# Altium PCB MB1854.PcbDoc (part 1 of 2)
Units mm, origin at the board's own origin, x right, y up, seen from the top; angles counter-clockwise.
Board outline 50.11 x 30.1 mm, 4 copper layers (Top Layer, Signal Layer 1, Signal Layer 2, Bottom Layer), stack 1.556 mm thick; 50 components, 31 nets, 194 pads, 158 vias.
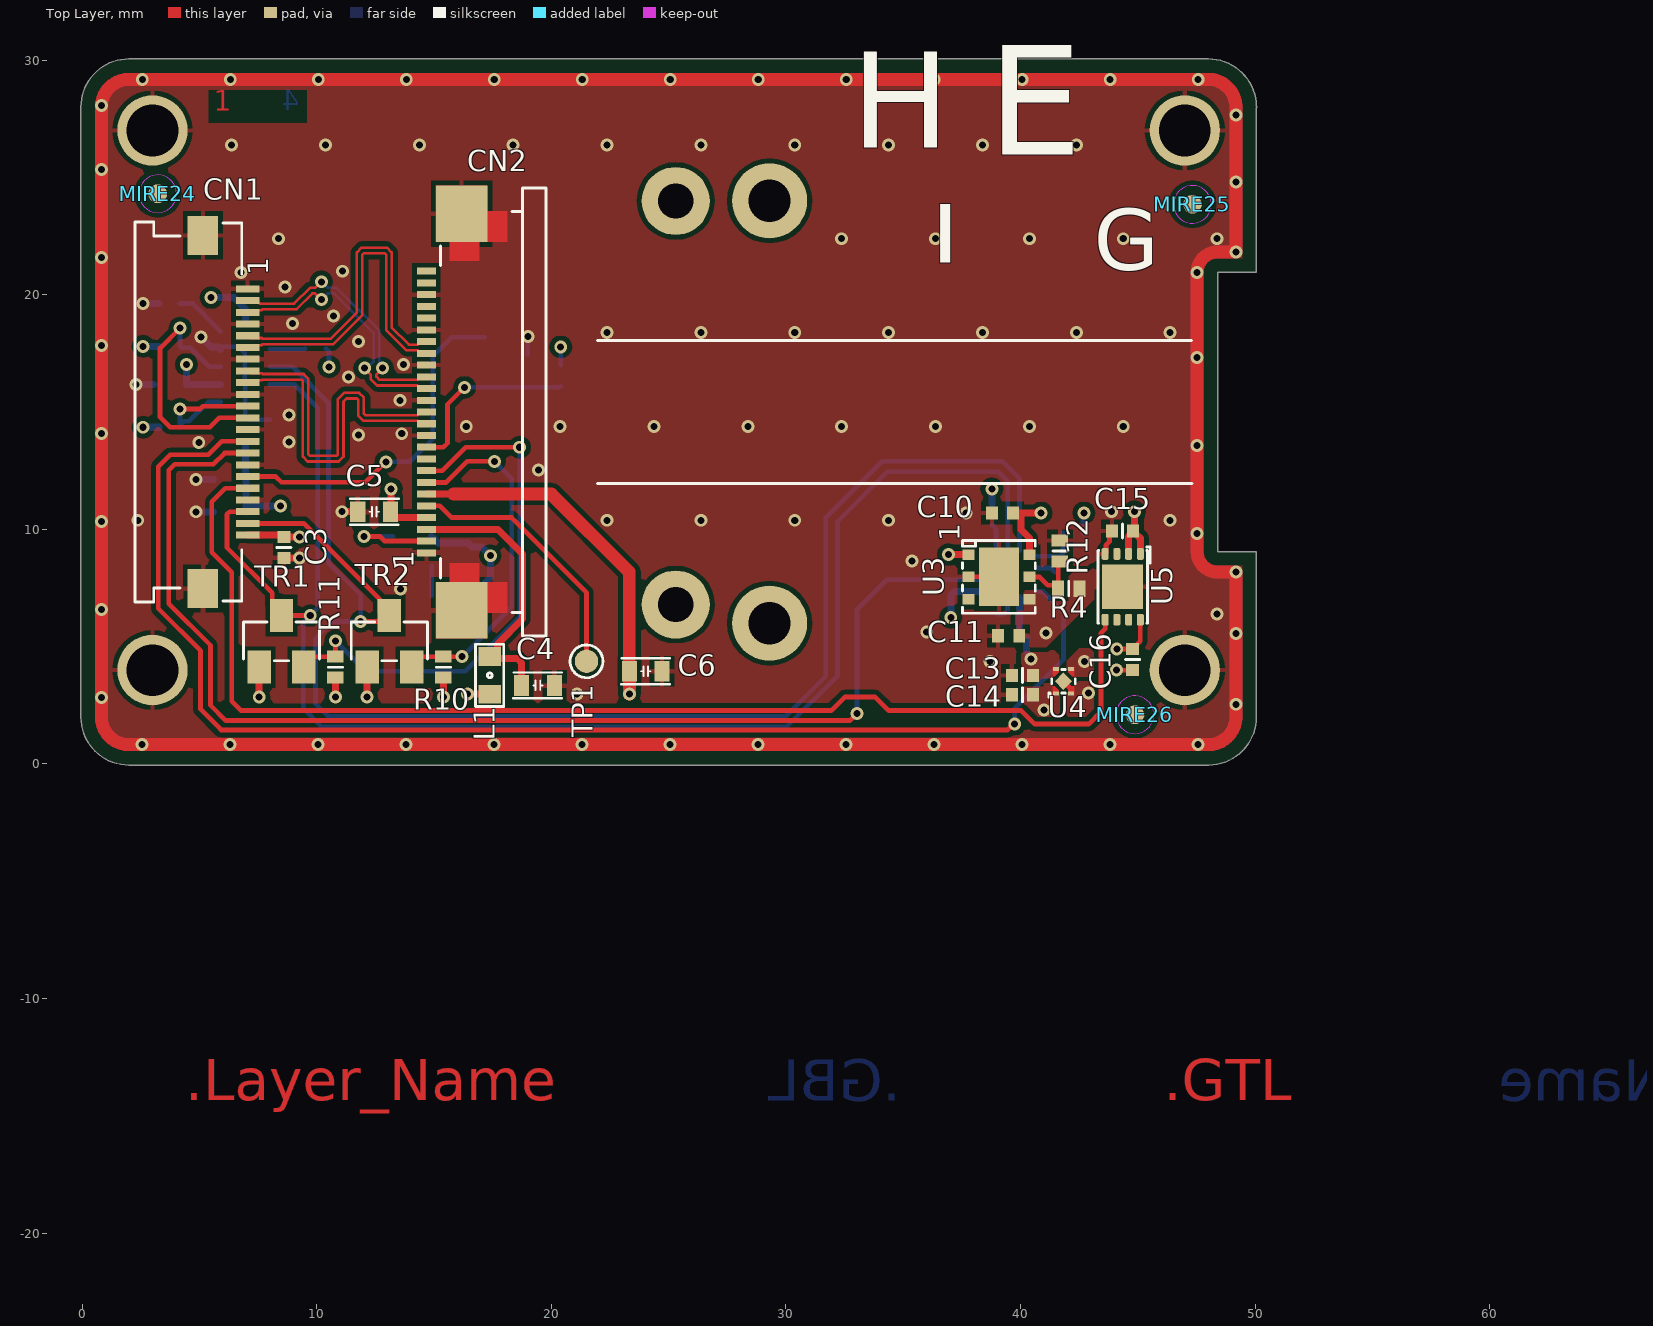
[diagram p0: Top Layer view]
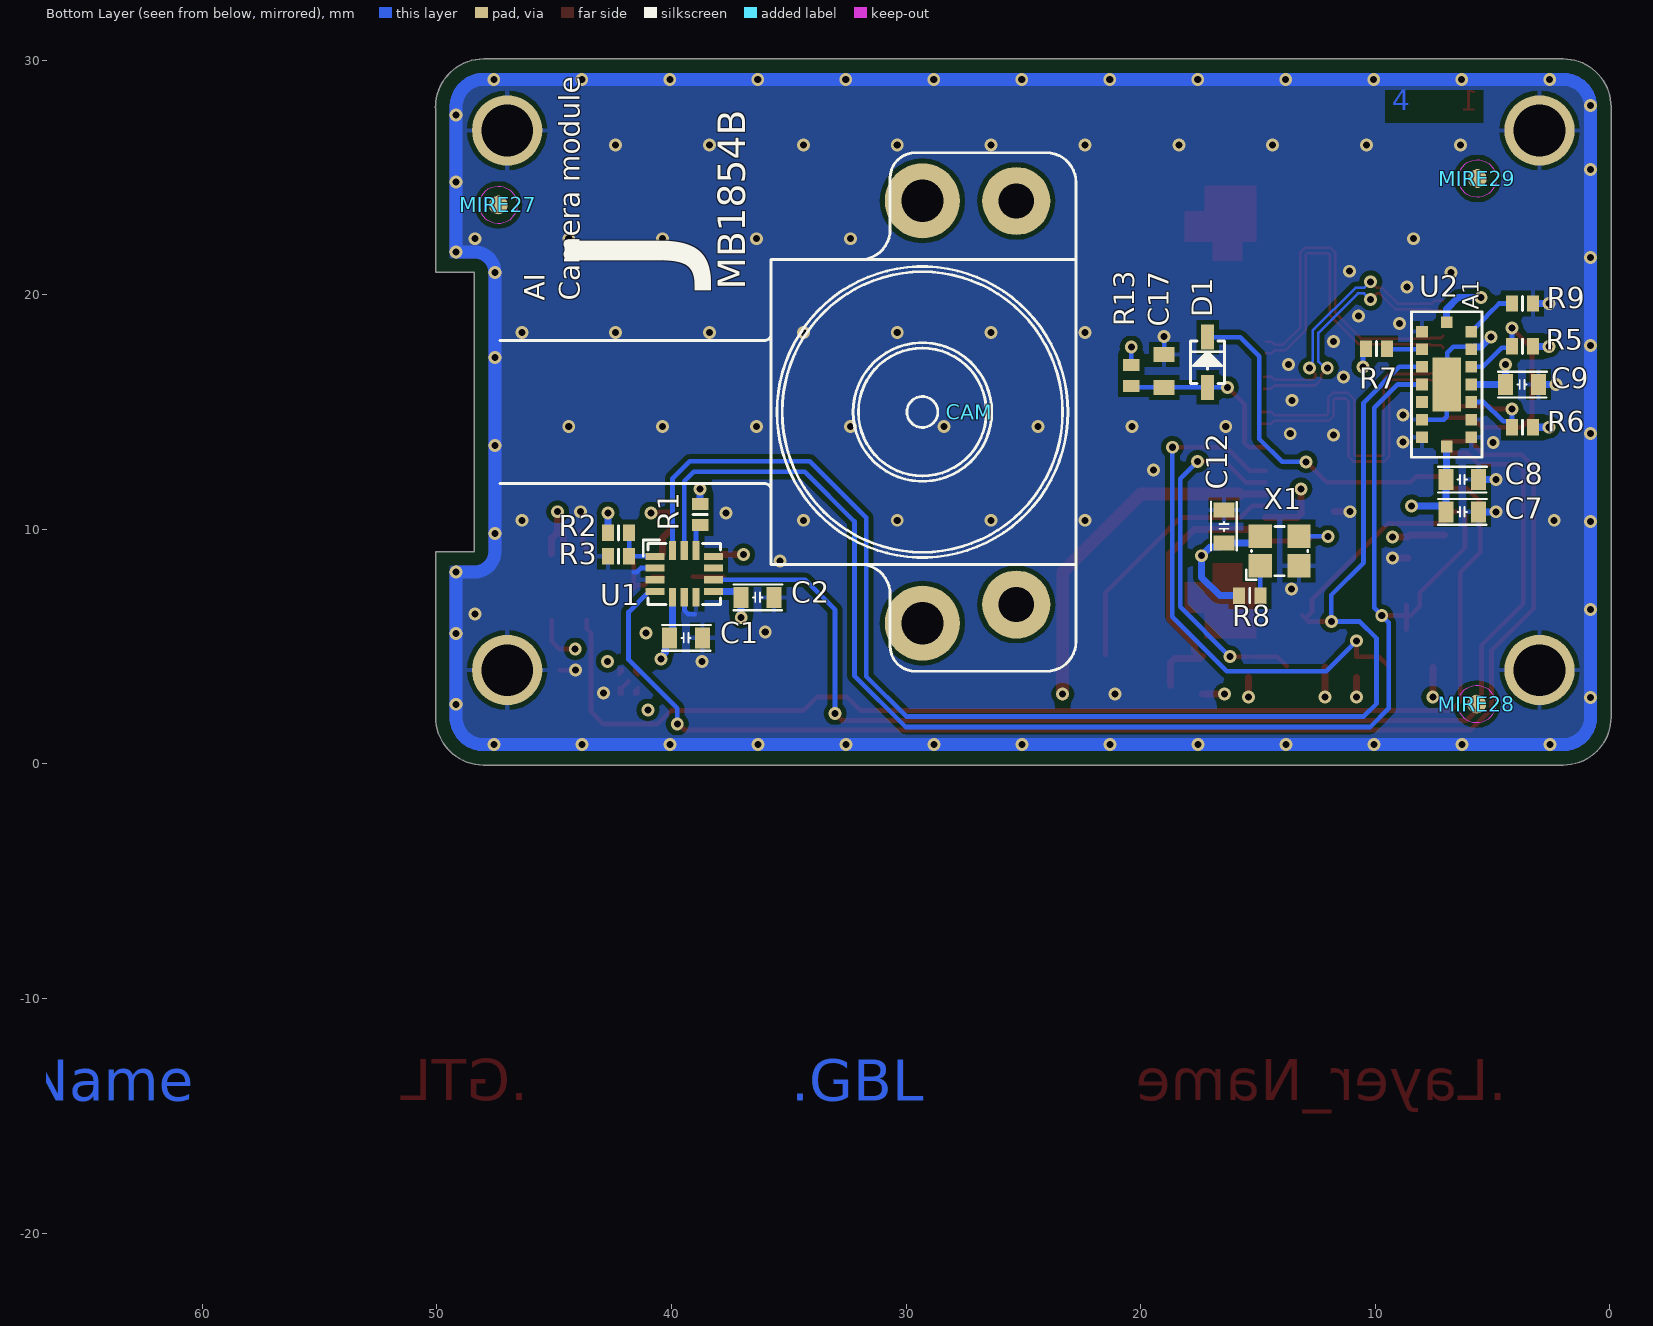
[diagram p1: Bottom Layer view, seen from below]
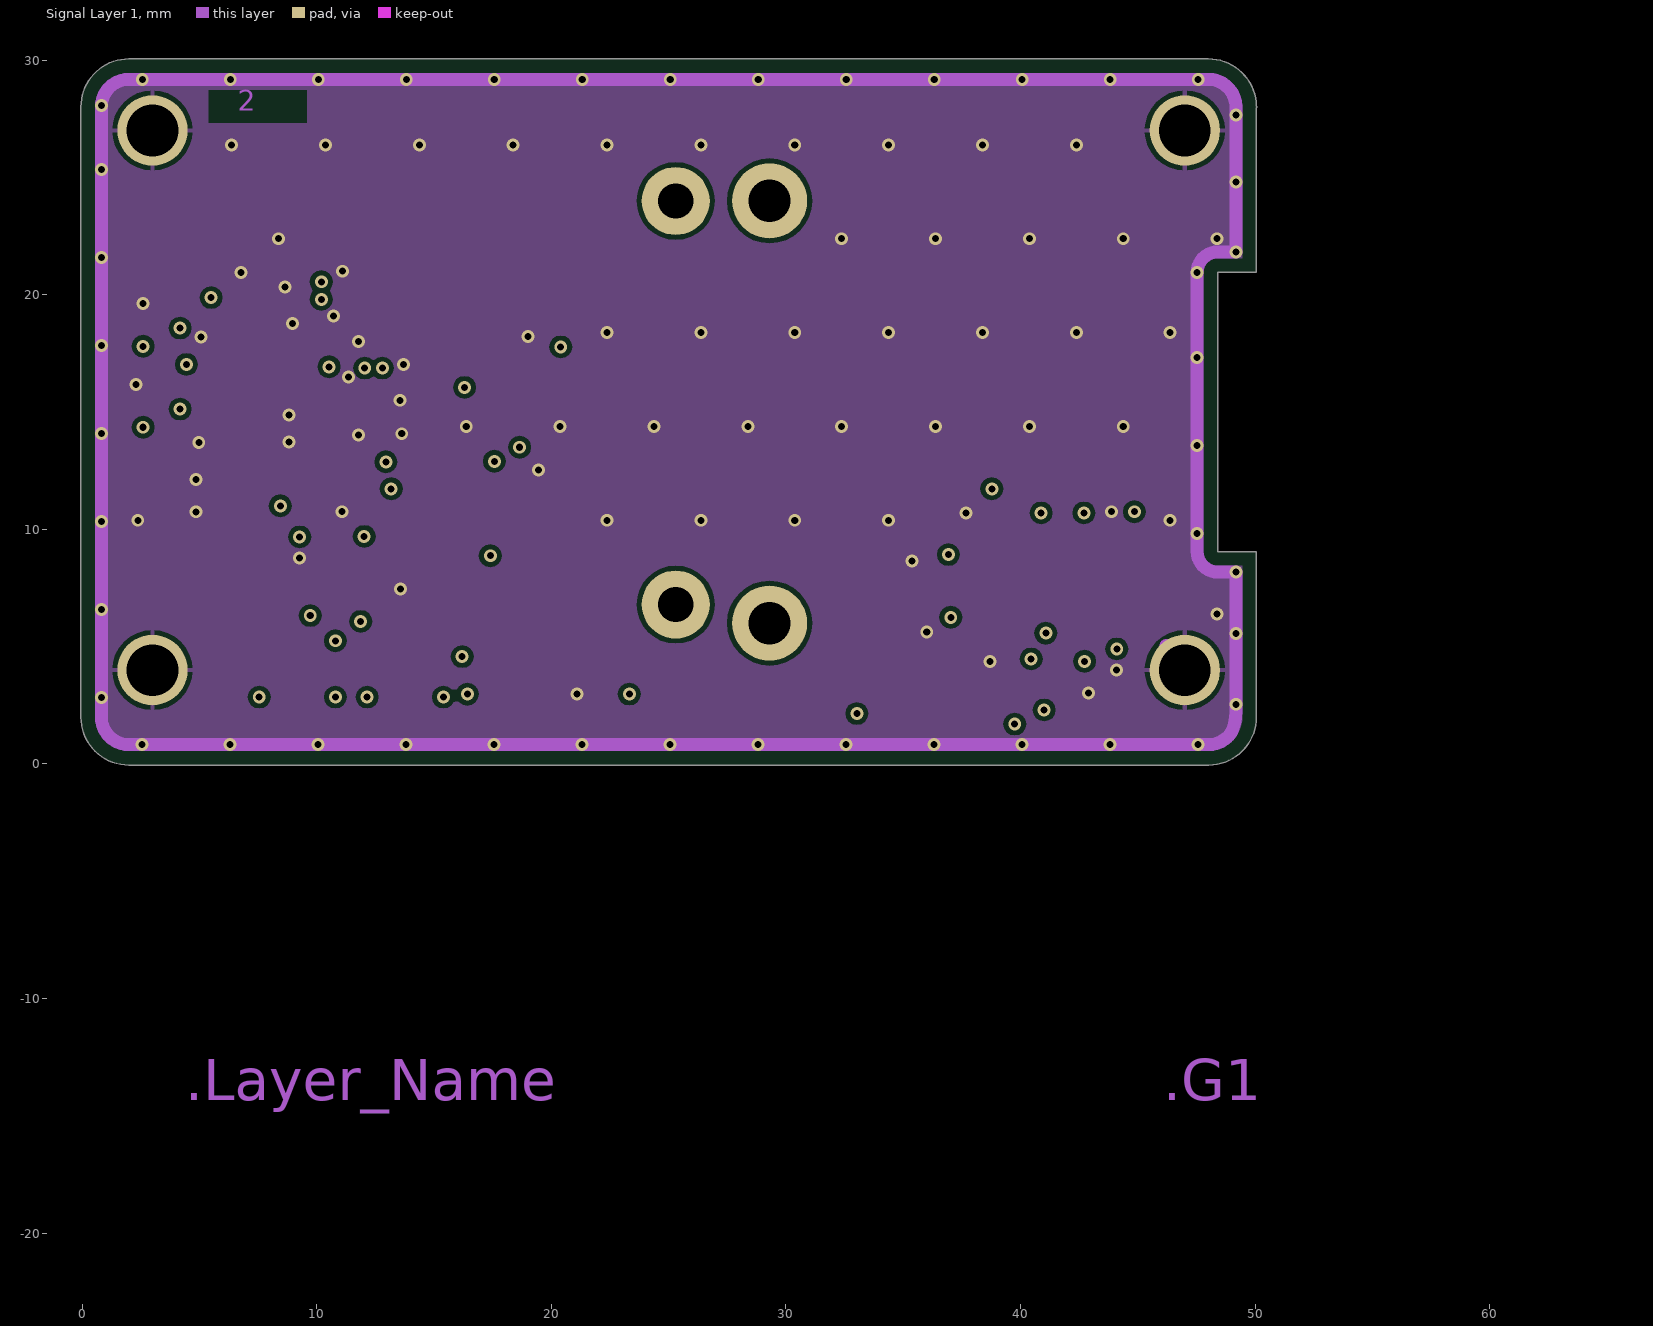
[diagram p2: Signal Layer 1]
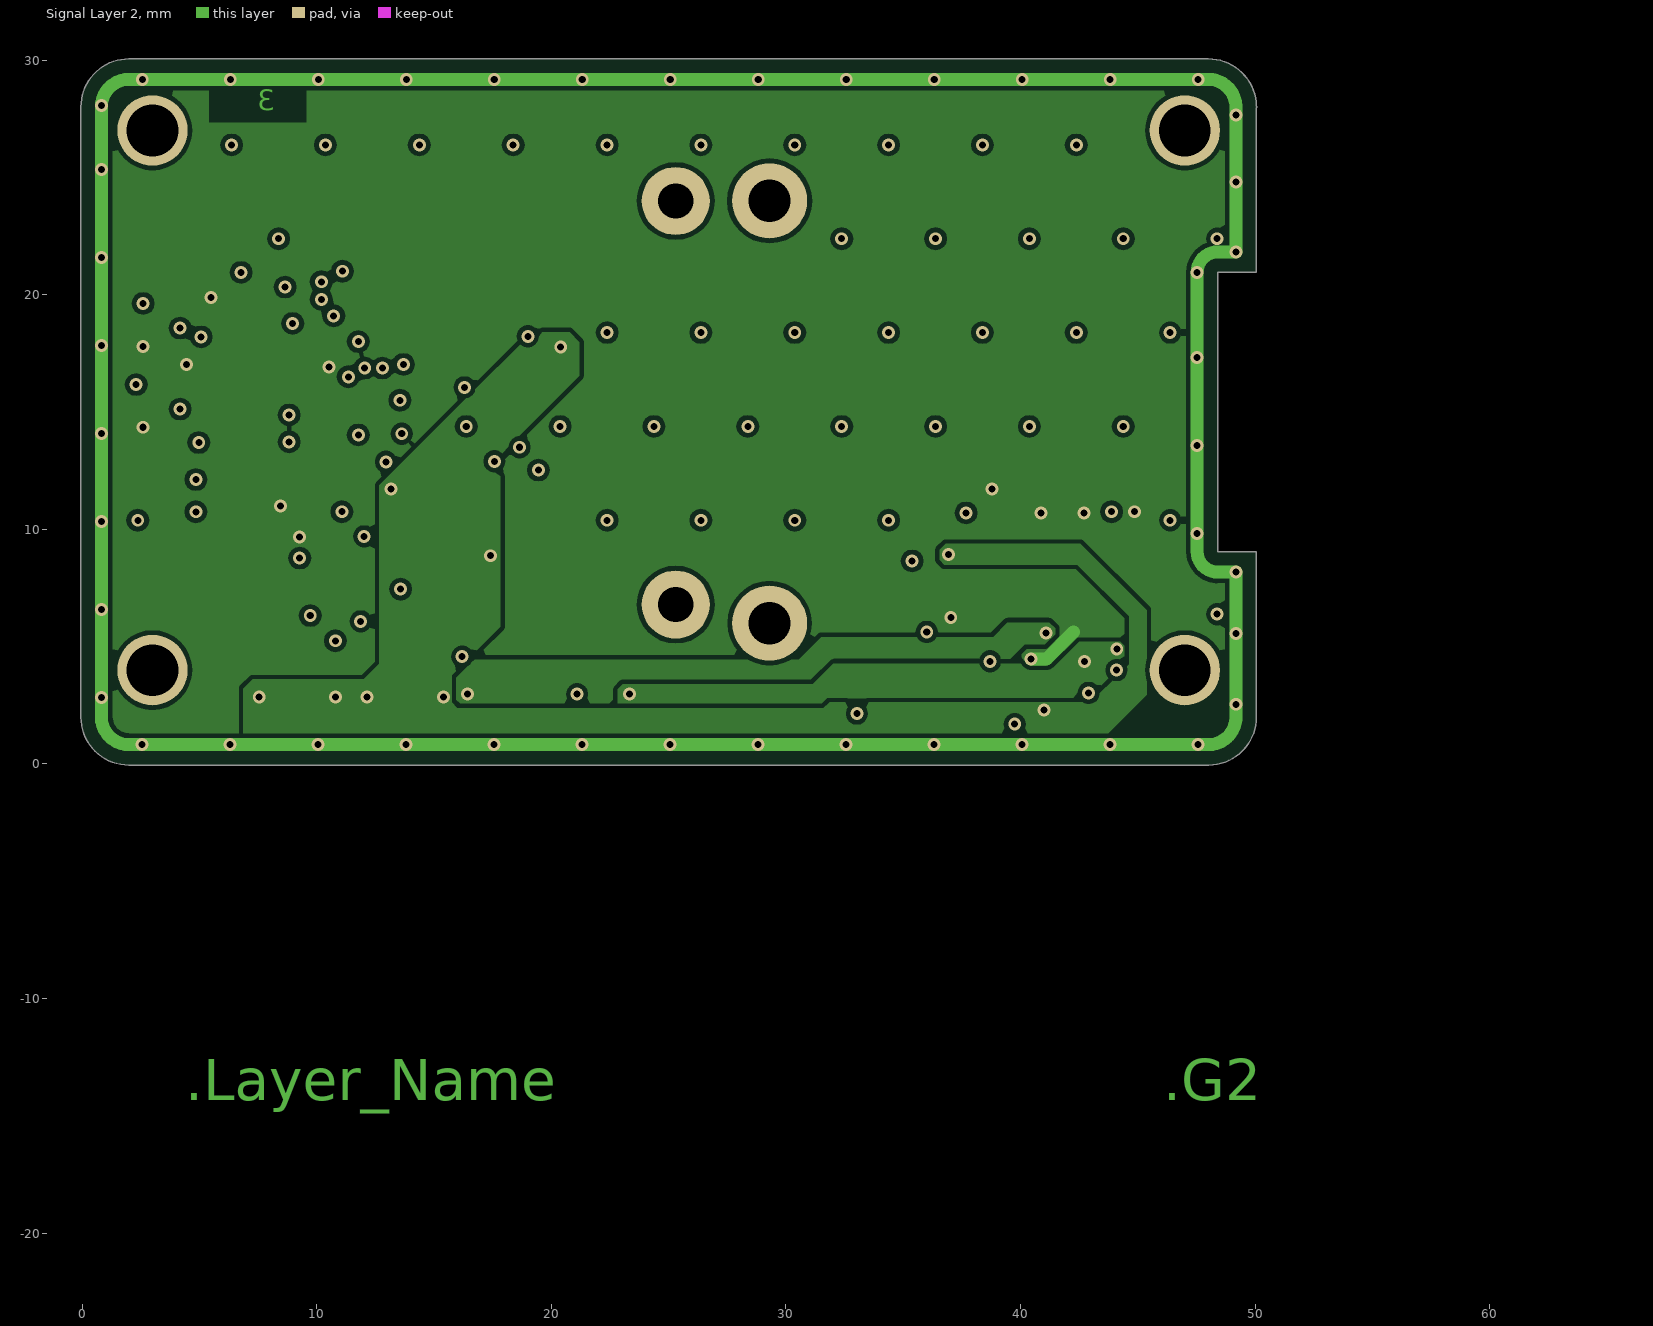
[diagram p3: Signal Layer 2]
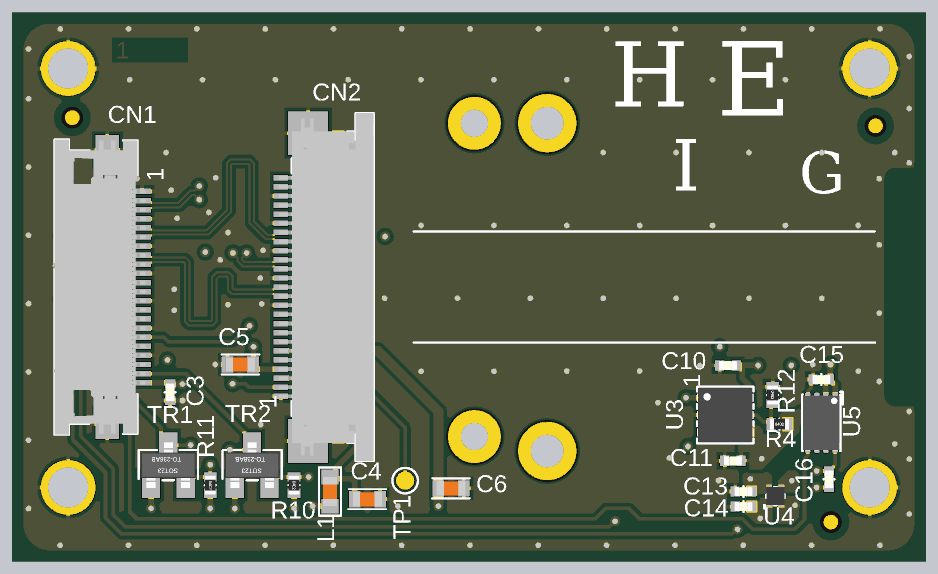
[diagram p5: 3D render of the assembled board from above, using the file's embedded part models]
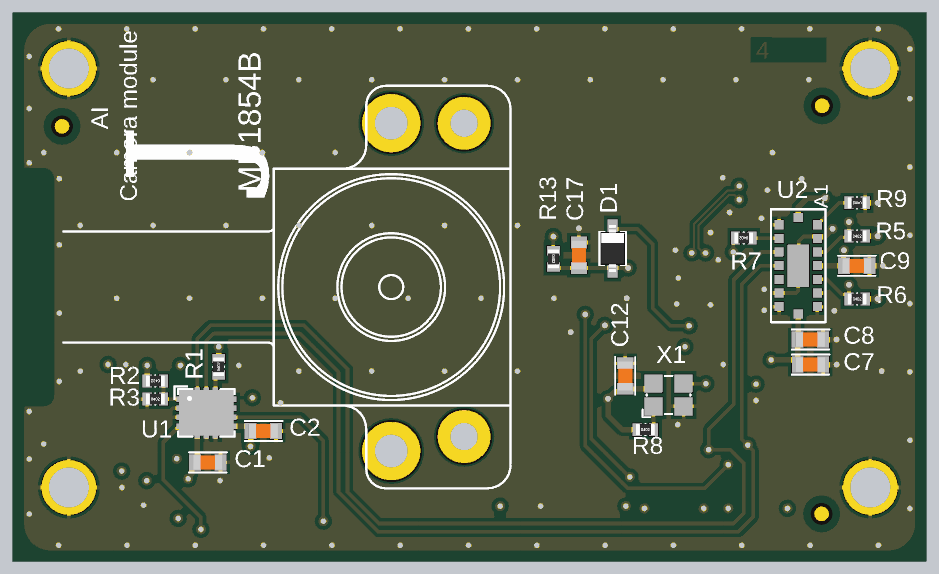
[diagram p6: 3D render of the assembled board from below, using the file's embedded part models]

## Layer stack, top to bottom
Top Solder: solder mask 0.015, Solder Resist, Dk 3.5
Top Layer: signal copper 0.037
Dielectric 2: prepreg 0.106, Dk 4.1
Signal Layer 1: signal copper 0.035
Dielectric 1: dielectric 1.2, Dk 4.2
Signal Layer 2: signal copper 0.035
Dielectric 3: prepreg 0.106, Dk 4.1
Bottom Layer: signal copper 0.037
Bottom Solder: solder mask 0.015, Solder Resist, Dk 3.5

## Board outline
-0.05,2 ccw(c2,2) 1.999,-0.05 ccw(c2,0) 2,-0.05 48.018,-0.05 ccw(c48.018,0) 48.022,-0.05 ccw(c48,2) 50.05,2 ccw(c50,2) 50.05,2.001 50.05,9 ccw(c50,9) 50,9.05 48.4,9.05 48.4,20.95 50,20.95 ccw(c50,21) 50.05,21 50.05,27.967 ccw(c50,28) 50.06,28 ccw(c50,28) 50.05,28.034 ccw(c48,28) 48,30.05 2.001,30.05 2,30.05 cw(c2,30) 2.001,30.05 2,30.05 ccw(c2,28) -0.05,28 ccw(c0,28) -0.05,28 -0.048,2.016 ccw(c0,2)

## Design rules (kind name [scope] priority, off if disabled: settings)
BoardOutlineClearance [All] p1: gap=0.3 ignorepadtopadclearanceinfootprint=FALSE except(0.6: Arc-OutlineEdge Track-OutlineEdge SMDPad-OutlineEdge THPad-OutlineEdge Via-OutlineEdge Fill-OutlineEdge Poly-OutlineEdge Region-OutlineEdge Text-OutlineEdge)
Clearance Clearance_Diff_GND [InNetClass('Paire_diff') vs InNet('GND')] p1: gap=0.3 ignorepadtopadclearanceinfootprint=TRUE except(0: Arc-Hole Track-Hole SMDPad-Hole THPad-Hole Via-Hole Fill-Hole Poly-Hole Region-Hole Text-Hole; 0.11: Arc-Arc Arc-Track Track-Track; 0.15: Arc-SMDPad Track-SMDPad; 0.2: SMDPad-SMDPad SMDPad-THPad SMDPad-Via SMDPad-Fill SMDPad-Poly SMDPad-Region SMDPad-Text)
Clearance [All] p2: gap=0.2 ignorepadtopadclearanceinfootprint=TRUE except(0: Arc-Hole Track-Hole SMDPad-Hole THPad-Hole Via-Hole Fill-Hole Poly-Hole Region-Hole Text-Hole; 0.11: Arc-Region Track-Via Track-Region SMDPad-Via SMDPad-Region THPad-Region Via-Region Fill-Region Poly-Region Region-Region; 0.13: Track-Track; 0.165: Arc-SMDPad Track-SMDPad)
ComponentClearance [All] p1: gap=0.2 collisioncheckmode=3 verticalgap=0.2 showdistances=FALSE
DiffPairsRouting DiffPairsRouting_CSI [InDifferentialPairClass('All Differential Pairs')] p1: maxlimit=0.254 minlimit=0.13 mostfreqgap=0.254 toplayer_maxgap=0.13 toplayer_prefgap=0.13 toplayer_minwidth=0.11 toplayer_maxwidth=0.11 toplayer_prefwidth=0.11 bottomlayer_maxgap=0.13 bottomlayer_prefgap=0.13 bottomlayer_minwidth=0.11 bottomlayer_maxwidth=0.11 bottomlayer_prefwidth=0.11 impedanceprofiledriven=TRUE impedanceprofileid={002CB140-4212-412A-BC71-8A519212D4D4} impedanceprofilevalue=100.000000 maxuncoupledlength=12.7
HoleSize [All] p1: absolutevalues=TRUE maxlimit=10 minlimit=0.025 maxpercent=80.000 minpercent=20.000
HoleToHoleClearance [All] p1: gap=0.45 allowstackedmicrovias=TRUE
Length LengthCSI [InNetClass('CSI')] p1: maxlimit=34.94 minlimit=33.67
MatchedLengths MatchedLengths_Inter_CSI [InNetClass('CSI')] p1: tolerance=1.27 checknetsindiffpair=FALSE checkdiffpairvsdiffpair=TRUE checkxsignals=TRUE checkothers=TRUE
MatchedLengths MatchedLengths_Intra_CSI [InDifferentialPairClass('CSI')] p2: tolerance=0.127 checknetsindiffpair=TRUE checkdiffpairvsdiffpair=FALSE checkxsignals=FALSE checkothers=FALSE
MinimumSolderMaskSliver [All] p1: minsoldermaskwidth=0.1
PlaneClearance [All] p1: clearance=0.6
PlaneConnect [All] p1: planeconnectstyle=Relief reliefexpansion=0.508 reliefentries=4 reliefconductorwidth=0.21 reliefairgap=0.21
PolygonConnect PolygonConnect_NO_FT [IsNamedPolygon('NO FT')] p1: connectstyle=Direct reliefconductorwidth=0.254 reliefentries=4 polygonreliefangle="90 Angle" airgapwidth=0.254
PolygonConnect [All] p2: thpad.connectstyle=Relief thpad.reliefconductorwidth=0.2 thpad.reliefentries=4 thpad.polygonreliefangle="90 Angle" thpad.airgapwidth=0.2 smdpad.connectstyle=Relief smdpad.reliefconductorwidth=0.2 smdpad.reliefentries=4 smdpad.polygonreliefangle="90 Angle" smdpad.airgapwidth=0.2 via.connectstyle=Direct via.reliefconductorwidth=0.2 via.reliefentries=4 via.polygonreliefangle="90 Angle" via.airgapwidth=0.2
RoutingVias [All] p1: holewidth=0.3 width=0.55 viastyle="Through Hole" minholewidth=0.3 minwidth=0.55 maxholewidth=0.3 maxwidth=0.55
SilkToSilkClearance [All] p1: silktosilkclearance=0.2
SilkToSolderMaskClearance [IsPad] p1: minsilkscreentomaskgap=0.2 clearancetoexposedcopper=TRUE
SolderMaskExpansion [All] p1: expansion=0.102 istentingtop=FALSE
ViasUnderSMD [All] p1: allowed=FALSE
Width [All] p1: maxlimit=1 minlimit=0.1 preferedwidth=0.2
21 further rules are at their usual default settings.

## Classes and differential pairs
component class U_MB1854: C1 C2 C3 C4 C5 C6 C7 C8 C9 C10 C11 C12 C13 C14 C15 C16 C17 CN1 CN2 D1 L1 R1 R2 R3 R4 R5 R6 R7 R8 R9 R10 R11 R12 R13 TP1 TR1 TR2 U1 U2 U3 U4 U5 X1
differential pair CSI_D1: +CSI_D1_P -CSI_D1_N
differential pair CSI_D0: +CSI_D0_P -CSI_D0_N
differential pair CSI_CLK: +CSI_CLK_P -CSI_CLK_N

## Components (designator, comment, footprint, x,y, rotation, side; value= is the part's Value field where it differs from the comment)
C1 "Capacitor" C0603 39.375,5.375 r0 bottom value=100nF
C2 "Capacitor" C0603 36.325,7.1 r0 bottom value=100nF
C3 "Capacitor" C0402 8.6,9.225 r90 top value=1uF
C4 "Capacitor" C0603 19.428,3.35 r0 top value=100nF
C5 "Capacitor" C0603 12.45,10.75 r180 top value=100nF
C6 "Capacitor" C0603 24.023,3.95 r0 top value=100nF
C7 "Capacitor" C0603 6.292,10.745 r0 bottom value=4.7uF
C8 "Capacitor" C0603 6.295,12.12 r0 bottom value=100nF
C9 "Capacitor" C0603 3.745,16.168 r0 bottom value=100nF
C10 "Capacitor" C0402 39.228,10.7 r0 top value=10uF
C11 "Capacitor" C0402 39.493,5.461 r0 top value=10uF
C12 "Capacitor" C0603 16.453,10.125 r270 bottom value=100nF
C13 "Capacitor" C0402 40.075,3.775 r0 top value=1uF
C14 "Capacitor" C0402 40.078,2.95 r0 top value=1uF
C15 "Capacitor" C0402 44.35,9.925 r0 top value=1uF
C16 "Capacitor" C0402 44.775,4.45 r90 top value=10uF
C17 "Capacitor" C0603 19,16.75 r90 bottom value=100nF
CAM "Comment" CAM_DRAWING_AS-BC538A3M6-63 29.303,15 r270 bottom locked
CN1 "54548-2271" CON_MOLEX_54548-2271 6.803,15 r270 top value=FPC_54548-2271
CN2 "52437-2533" CON_MOLEX_52437-2533 15.425,15 r90 top
D1 "BAT60JFILM" DIO_SOD323 17.15,17.12 r90 bottom
L1 "BEAD" L0603 17.375,3.775 r90 top value="600R @ 100MHz"
MIRE24 "Comment" MIRE_PLACE_SMD_0P8MM 3.225,24.3 r180 top
MIRE25 "Comment" MIRE_PLACE_SMD_0P8MM 47.325,23.85 r180 top
MIRE26 "Comment" MIRE_PLACE_SMD_0P8MM 44.875,2.1 r180 top
MIRE27 "Comment" MIRE_PLACE_SMD_0P8MM 47.375,23.825 r180 bottom
MIRE28 "Comment" MIRE_PLACE_SMD_0P8MM 5.675,2.55 r180 bottom
MIRE29 "Comment" MIRE_PLACE_SMD_0P8MM 5.65,24.95 r180 bottom
R1 "Resistor" R0402 38.775,10.625 r90 bottom value=10K
R2 "" R0402 42.253,9.85 r0 bottom value=4K7
R3 "" R0402 42.253,8.85 r180 bottom value=4K7
R4 "Resistor" R0402 42.053,7.475 r0 top value=19K6
R5 "Resistor" R0402 3.725,17.8 r180 bottom value=47K
R6 "Resistor" R0402 3.725,14.35 r180 bottom value=47K
R7 "Resistor" R0402 9.95,17.7 r0 bottom value=47K
R8 "Resistor" R0402 15.35,7.175 r180 bottom value=10K
R9 "Resistor" R0402 3.725,19.625 r0 bottom value=47K
R10 "Resistor" R0402 15.4,4.125 r270 top value=4K7
R11 "Resistor" R0402 10.8,4.125 r270 top value=4K7
R12 "Resistor" R0402 41.678,9.075 r270 top value=15K
R13 "Resistor" R0402 20.4,16.55 r270 bottom value=10K
TP1 "Test Point" TP_SMD_1MM 21.5,4.375 r0 top
TR1 "BSN20" MOS_SOT23 8.5,5.225 r0 top value=FDV301N
TR2 "BSN20" MOS_SOT23 13.1,5.225 r0 top value=FDV301N
U1 "ISM330DLCTR" ICC_LGA14_3X2P5_P050 39.453,8.1 r180 bottom
U2 "VL53L5CXV0GC/1" ICC_LGA16_6P4X3_P075_H1P5 6.958,16.175 r90 bottom
U3 "ST1L05BPUR" ICC_DFN6-EPAD_3X3_P095 39.078,7.975 r270 top
U4 "LD39020" REG_XDFN4-EPAD_CASE-711AJ_1X1_H0P4_P065 41.828,3.525 r0 top value=LD39020ADTPU18R
U5 "ST1L08SPU12R" ICC_DFN8-EPAD_2X3_P050_H0P9 44.353,7.55 r0 top
X1 "OSCILLATOR_4_PINS" OSC_NDK_NZ2520SB_4P 14.078,9.075 r180 bottom value=24MHz

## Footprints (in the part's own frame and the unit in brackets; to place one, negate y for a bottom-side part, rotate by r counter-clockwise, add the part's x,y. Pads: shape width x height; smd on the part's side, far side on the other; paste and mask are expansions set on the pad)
C0402 [mm]
  rect 0.51x0.56 smd mask+0.05: 1(-0.45,0) 2(0.45,0)
  silkscreen extent 0,-0.3 0,0.3, body extent -0.5,-0.3 0.5,0.3, height 0.4
C0603 [mm]
  rect 0.64x0.89 smd mask+0.05: 1(-0.7,0) 2(0.7,0)
  silkscreen extent -1.05,-0.55 1.02,0.55, body extent -0.9,-0.5 0.9,0.5, height 1.4
CAM_DRAWING_AS-BC538A3M6-63 [mm] "MCD-02783"
  round 3.2 hole 1.8 mask+0.102: 1(-9,0) 1(9,0)
  round 2.9 hole 1.5 mask+0.102: 1(-8.993,4) 1(8.207,4)
  silkscreen extent -11.05,-18 11.05,6.55, body extent -23.01,-6.9 11.05,12.51, height 24.2
CON_MOLEX_52437-2533 [mm] "MCD-XXXXX"
  rect 0.3x0.8 smd mask+0.05: 1(-6,0.75) 2(-5.5,0.75) 3(-5,0.75) 4(-4.5,0.75) 5(-4,0.75) 6(-3.5,0.75) 7(-3,0.75) 8(-2.5,0.75) 9(-2,0.75) 10(-1.5,0.75) 11(-1,0.75) 12(-0.5,0.75) 13(0,0.75) 14(0.5,0.75) 15(1,0.75) 16(1.5,0.75) 17(2,0.75) 18(2.5,0.75) 19(3,0.75) 20(3.5,0.75) 21(4,0.75) 22(4.5,0.75) 23(5,0.75) 24(5.5,0.75) 25(6,0.75)
  rect 2.4x2.2 smd mask+0.05: S1(-8.45,-0.75) S2(8.45,-0.75)
  Top Layer region: 9.65,0.35 7.25,0.35 7.25,-0.25 6.45,-0.25 6.45,-1.5 7.25,-1.5 7.25,-2.7 8.55,-2.7 8.55,-1.85 9.65,-1.85
  Top Layer region: -9.65,0.35 -7.25,0.35 -7.25,-0.25 -6.45,-0.25 -6.45,-1.5 -7.25,-1.5 -7.25,-2.7 -8.55,-2.7 -8.55,-1.85 -9.65,-1.85
  silkscreen extent -9.55,-4.35 9.55,0.15, body extent -9.55,-4.35 9.55,0.85, height 2
CON_MOLEX_54548-2271 [mm] "MCD-02565"
  rect 0.3x1 smd paste+0 mask+0.05: 1(-5.25,0.25) 2(-4.75,0.25) 3(-4.25,0.25) 4(-3.75,0.25) 5(-3.25,0.25) 6(-2.75,0.25) 7(-2.25,0.25) 8(-1.75,0.25) 9(-1.25,0.25) 10(-0.75,0.25) 11(-0.25,0.25) 12(0.25,0.25) 13(0.75,0.25) 14(1.25,0.25) 15(1.75,0.25) 16(2.25,0.25) 17(2.75,0.25) 18(3.25,0.25) 19(3.75,0.25) 20(4.25,0.25) 21(4.75,0.25) 22(5.25,0.25)
  rect 1.65x1.3 smd paste+0 mask+0.05: S1(-7.525,-1.65) S2(7.525,-1.65)
  silkscreen extent -8.1,-4.55 8.1,0, body extent -8.1,-4.55 8.1,0.45, height 1.18
DIO_SOD323 [mm]
  rect 1.06x0.54 smd mask+0.05: 1(-1.07,0) 2(1.07,0)
  silkscreen extent -0.9,-0.72 0.9,0.72, body extent -1.3,-0.78 1.3,0.78, height 1.17
ICC_DFN6-EPAD_3X3_P095 [mm]
  rect 0.45x0.5 smd mask+0.05: 1(-0.95,-1.3) 2(0,-1.3) 3(0.95,-1.3) 4(0.95,1.3) 5(0,1.3) 6(-0.95,1.3)
  rect 2.5x1.7 smd mask+0.05: EP(0,0)
  silkscreen extent -1.55,-1.55 1.55,1.55, body extent -1.55,-1.55 1.55,1.55, height 1
ICC_DFN8-EPAD_2X3_P050_H0P9 [mm] "MCD-02312"
  rrect50% 0.3x0.5 smd mask+0.05: 1(0.75,1.4) 2(0.25,1.4) 3(-0.25,1.4) 4(-0.75,1.4) 5(-0.75,-1.4) 6(-0.25,-1.4) 7(0.25,-1.4) 8(0.75,-1.4)
  rect 1.75x1.9 smd mask+0.05: 9(0,0)
  silkscreen extent -1.05,-1.55 1.17,1.7, body extent -1,-1.52 1,1.52, height 0.9
ICC_LGA14_3X2P5_P050 [mm] "MCD-01387"
  rect 0.8x0.3 smd mask+0.05: 1(-1.25,0.75) 2(-1.25,0.25) 3(-1.25,-0.25) 4(-1.25,-0.75) 8(1.25,-0.75) 9(1.25,-0.25) 10(1.25,0.25) 11(1.25,0.75)
  rect 0.3x0.8 smd mask+0.05: 5(-0.5,-1) 6(0,-1) 7(0.5,-1) 12(0.5,1) 13(0,1) 14(-0.5,1)
  silkscreen extent -1.75,-1.3 1.55,1.45, body extent -1.55,-1.3 1.55,1.3, height 0.86
ICC_LGA16_6P4X3_P075_H1P5 [mm] "MCD-02257"
  rect 0.5x0.5 smd mask+0.05: A1(2.25,-1.05) A2(1.5,-1.05) A3(0.75,-1.05) A4(0,-1.05) A5(-0.75,-1.05) A6(-1.5,-1.05) A7(-2.25,-1.05) B1(2.65,0) B7(-2.65,0) C1(2.25,1.05) C2(1.5,1.05) C3(0.75,1.05) C4(0,1.05) C5(-0.75,1.05) C6(-1.5,1.05) C7(-2.25,1.05)
  rect 2.316x1.2 smd mask+0.05: B4(0,0)
  silkscreen extent -3.1,-1.5 3.1,1.5, body extent -3.1,-1.5 3.1,1.5, height 1.51
L0603 [mm]
  rect 0.8x0.95 smd mask+0.05: 1(-0.8,0) 2(0.8,0)
  silkscreen extent -1.33,-0.6 1.33,0.6, body extent -0.87,-0.47 0.87,0.47, height 0.95
MIRE_PLACE_SMD_0P8MM [mm]
  round 0.8 smd paste-10 mask+0.2: 1(0,0)
  Top Layer keep-out circle w0.01: c0,0 r0.804
MOS_SOT23 [mm]
  rect 1x1.4 smd mask+0.05: 1(-0.95,-1.1) 2(0.95,-1.1) 3(0,1.1)
  silkscreen extent -1.63,-0.82 1.63,0.82, body extent -1.56,-1.25 1.56,1.25, height 1.1
OSC_NDK_NZ2520SB_4P [mm]
  rect 1x1 smd mask+0.05: 1(-0.825,-0.625) 2(0.825,-0.625) 3(0.825,0.625) 4(-0.825,0.625)
  silkscreen extent -1.43,-1.22 1.2,1.05, body extent -1.3,-1.05 1.3,1.05, height 0.91
R0402 [mm]
  rect 0.51x0.7 smd mask+0.05: 1(-0.45,0) 2(0.45,0)
  silkscreen extent 0,-0.3 0,0.3, body extent -0.52,-0.3 0.52,0.3, height 0.4
REG_XDFN4-EPAD_CASE-711AJ_1X1_H0P4_P065 [mm] "MCD-01613"
  rect 0.26x0.17 smd paste-10 mask-10: 1(-0.325,-0.515) 2(0.325,-0.515) 3(0.325,0.515) 4(-0.325,0.515)
  rect 0.52x0.52 smd rot 45 paste+0 mask+0.038: 5(0,0)
  Top Layer region: 0.455,-0.6 0.195,-0.6 0.195,-0.39 0.375,-0.21 0.455,-0.21
  Top Layer region: -0.455,-0.6 -0.195,-0.6 -0.195,-0.39 -0.375,-0.21 -0.455,-0.21
  Top Layer region: 0.455,0.6 0.195,0.6 0.195,0.39 0.375,0.21 0.455,0.21
  Top Layer region: -0.455,0.6 -0.195,0.6 -0.195,0.39 -0.375,0.21 -0.455,0.21
  Top Layer lines w0.001: 0.035,-0.33 0.035,-0.33
  silkscreen extent -0.63,-0.67 0.5,0.5, body extent -0.5,-0.5 0.5,0.5, height 0.44
TP_SMD_1MM [mm]
  round 1 smd paste-10 mask+0.05: 1(0,0)
  silkscreen extent -0.7,-0.7 0.7,0.7

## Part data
C1 C2 C4 C5 C6 C8 C9 C12 C17: library part MCD-00211, "Capacitor, MLCC, 100nF, 16V, X7R, 10%, 0603, T=0,8mm", Manufacturer=YAGEO, Manufacturer_Part_Number=CC0603KRX7R7BB104, Package=0603
C3 C13 C14 C15: library part MCD-00095, "Capacitor, MLCC, 1uF, 25V, X5R, +/-10%, 0402, T=0,5mm", Alternate_Manufacturer=MURATA, Alternate_Manufacturer_Part_Number=GRM155R60J105KE19, Manufacturer_Part_Number=GRM155R61E105KA12, Package=0402
C7: library part MCD-00009, "Capacitor, MLCC, 4.7uF, 16V, X5R, +/-10%, 0603, T=0.8mm", Alternate_Manufacturer=N/A, Manufacturer=YAGEO, Manufacturer_Part_Number=CC0603KRX5R7BB475, Package=0603
C10 C11 C16: library part MCD-01532, "Capacitor, MLCC, 10uF, 10V, X5R, +/-20%, 0402, T=0.5mm", Manufacturer=MURATA, Manufacturer_Part_Number=GRM155R61A106ME11, Package=0402
CN1: library part MCD-02565, "Socket_FFC/FPC, 22pins, 0.5mm, SMD, T=1.2mm", Manufacturer=MOLEX
CN2: library part MCD-02922, "Socket_FFC/FPC, 25pins, 0.5mm, RA, SMD, T=2mm", Manufacturer=MOLEX
D1: library part MCD-00034, Manufacturer=STMICROELECTRONICS, Manufacturer_HQ_COO=EU
L1: library part MCD-00047, "SMD Chip ferrite bead, 600R@100MHz +/-25%, 350mA, 500mohm DC, 0603, T=0.8mm", Manufacturer=TAI-TECH, Manufacturer_Part_Number=FCM1608KF-601T03, Package=0603
R1: library part MCD-00053, "Resistor, 10K, 0402, +/-1%, 1/16W", Alternate_Manufacturer=N/A, Manufacturer=YAGEO, Manufacturer_Part_Number=RC0402FR-0710KL, Package=0402
R2 R3 R10 R11: library part MCD-00065, "Resistor,4K7,0402,1%,1/16W", Alternate_Manufacturer=YAGEO, Alternate_Manufacturer_Part_Number=RT0402FRE074K7L, Manufacturer_Part_Number=RC0402FR-074K7L, Package=0402
R4: library part MCD-00344, "Resistor, 19K6, 0402, +/-1%, 1/16W", Manufacturer=YAGEO, Manufacturer_Part_Number=RC0402FR-0719K6L, Package=0402
R5 R6 R7 R9: library part MCD-00063, "Resistor, 47K, 0402, +/-1%, 1/16W", Alternate_Manufacturer=N/A, Manufacturer=YAGEO, Manufacturer_Part_Number=RC0402FR-0747KL, Package=0402
R8 R13: library part MCD-00053, "Resistor, 10K, 0402, +/-1%, 1/16W", Manufacturer=YAGEO, Manufacturer_Part_Number=RC0402FR-0710KL, Package=0402
R12: library part MCD-01943, "Resistor, 15K, 0402, +/-1%, 1/16W", Manufacturer=YAGEO, Manufacturer_Part_Number=RC0402FR-0715KL, Package=0402
TP1: library part MCD-00074, "Test Point 1mm", Manufacturer=N/A
TR1 TR2: library part MCD-02156, "MOSFET, N-Channel , Vds: 25V, Id: 0,22A, Vgs(th): 1.06V, Vgs(max): +/-8V, Rdson:5ohm@Vgs=2.7V, Qg=0,49nC", Alternate_Manufacturer=N/A, Manufacturer="ON SEMICONDUCTOR", Manufacturer_Part_Number=FDV301N, Package=SOT23-3
U1: library part MCD-01714, "iNEMO inertial module: 3D accelerometer and 3D gyroscope, with digital output for industrial applications", Manufacturer=STMICROELECTRONICS, Manufacturer_HQ_COO=EU, Package=LGA-14L
U2: library part MCD-02590, "Time-of-Flight 8x8 multizone ranging sensor with wide field of view", Manufacturer=STMICROELECTRONICS, Package="Optical LGA16"
U3: library part MCD-00581, "LDO Linear Voltage Regulator IC Positive Adjustable 1 Output Adjustable 1.3A 6-DFN (3x3)", Manufacturer=STMICROELECTRONICS, Manufacturer_HQ_COO=EU, Package="DFN6 (3x3)"
U4: library part MCD-02224, "LDO, output 1V8, 200 mA very low quiescent current", Alternate_Manufacturer=N/A, Manufacturer=STMICROELECTRONICS, Manufacturer_HQ_COO=EU, Manufacturer_Part_Number=LD39020ADTPU18R, Package=DFN4
U5: library part MCD-02920, "LDO, fixe 1V2, Input 1V to 5.5V, 0.8A", Manufacturer=STMICROELECTRONICS, Package=DFN-8
X1: library part MCD-01976, "Oscillator, SPXO, 24Mhz, +/-50ppm, 3V3, square wave, 2.5x2mm", Manufacturer=NDK, Manufacturer_Part_Number=NZ2520SH-24MHZ-END4869D, Package=2.5x2mm

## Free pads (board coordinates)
  round 3 hole 2.2 paste+0.025 mask+0.05: 1(3,4) 1(3,27) 1(47,4) 1(47,27)
  round 0.508 on Mech16: 1(16.06,-21.253) 1(64.915,-21.261)

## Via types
v1: diameter 0.55, hole 0.3, Top Layer to Bottom Layer, tented both sides, 158 vias

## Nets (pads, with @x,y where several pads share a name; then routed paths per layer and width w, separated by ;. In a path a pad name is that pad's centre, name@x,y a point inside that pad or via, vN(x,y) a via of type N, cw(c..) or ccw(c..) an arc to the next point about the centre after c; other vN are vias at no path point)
1V2: C6.1 C16.2 CN2.6 U4.3 U5.8 | length 17.3
  Top Layer w0.2: v1(44.1,4.9) C16.2@44.775,4.9 44.8,4.9 44.955,5.055 44.955,5.08 45.103,5.228 U5.8@45.103,6.15
  Top Layer w0.3: CN2.6@14.675,11.5 15.825,11.5
  Top Layer w0.55: 15.825,11.5 20,11.5 23.323,8.177 23.323,3.781 23.324,3.78 v1(23.324,2.976)
  other v1: 42.725,4.375
1V8: C5.1 C12.2 C14.2 CN2.4 R8.1 R10.2 R11.2 R13.1 TR1.1 TR2.1 U3.1 U4.1 X1.4 | length 14.2
  Top Layer w0.3: v1(7.55,2.85) TR1.1@7.55,4.125 ; v1(10.8,2.85) R11.2@10.8,3.675 ; v1(12.15,2.85) TR2.1@12.15,4.125 ; v1(13.175,11.725) 13.175,10.775 C5.1@13.15,10.75 13.15,10.67 13.32,10.5 CN2.4@14.675,10.5 ; v1(15.4,2.85) R10.2@15.4,3.675 ; v1(36.925,8.925) U3.1@37.778,8.925
  Bottom Layer w0.2: R13.1@20.4,17 v1(20.4,17.775)
  Bottom Layer w0.3: X1.4@14.903,9.7 15.178,9.425 C12.2@16.453,9.425 16.623,9.255 17.02,9.255 v1(17.4,8.875) 17.4,7.95 16.625,7.175 R8.1@15.8,7.175
  other v1: 41,2.3
2V8: C11.2 L1.1 R4.2 U3.4 | length 1
  Top Layer w0.3: v1(16.422,2.975) L1.1@17.375,2.975
  other v1: 41.075,5.575
3V3: C1.2 C2.2 C3.2 C7.2 C8.2 C9.2 C10.2 C13.2 C15.2 CN1.22 R1.2 R2.2 R5.2 R6.2 R7.2 U1.5 U1.8 U2.A4 U2.B1 U2.B7 U3.6 U4.4 U5.1 U5.2 | length 28
  Top Layer w0.3: CN1.22@7.053,9.75 8.525,9.75 cw(c8.525,9.675) C3.2@8.6,9.675 v1@9.225,9.675 ; U3.6@40.378,8.925 40.378,9.622 40.014,9.986 40.014,10.613 39.928,10.7 v1(40.875,10.7) ; U5.2@44.603,8.95 44.603,9.703 44.8,9.9 44.905,9.795 44.927,9.795 45.103,9.619 U5.1@45.103,8.95 ; C15.2@44.8,9.925 44.848,9.973 44.848,10.748 v1(44.85,10.75)
  Signal Layer 2 w0.55: v1(40.45,4.475) 41.1,4.475 42.25,5.625
  Bottom Layer w0.2: R7.2@10.4,17.7 10.525,17.575 v1(10.525,16.925)
  Bottom Layer w0.3: v1(2.6,14.35) R6.2@3.275,14.35 ; v1(2.6,17.8) R5.2@3.275,17.8 ; C9.2@4.445,16.168 C9.2@4.45,16.173 ; v1(4.45,17.025) C9.2@4.45,16.173 ; v1(5.5,19.875) 6.475,19.875 6.958,19.392 U2.B1@6.958,18.825 ; U2.A4@5.908,16.175 4.452,16.175 C9.2@4.45,16.173 ; U2.B7@6.958,13.525 6.958,12.157 C8.2@6.995,12.12 6.992,12.117 C7.2@6.992,10.83 ; C7.2@6.992,10.745 C7.2@6.992,10.83 ; v1(8.45,11) 7.162,11 C7.2@6.992,10.83 ; v1(37.025,6.25) C2.2@37.025,7.1 37.025,7.18 37.195,7.35 U1.8@38.203,7.35 ; R1.2@38.775,11.075 v1(38.775,11.725) ; U1.5@39.953,7.1 39.953,5.497 C1.2@40.075,5.375 ; C1.2@40.1,5.502 40.245,5.357 40.245,4.748 40.45,4.543 v1(40.45,4.475) ; R2.2@42.701,9.851 v1(42.701,10.699)
  other v1: 9.275,9.675
CAM_CLK: CN2.2 X1.3 | length 3.8
  Top Layer w0.2: v1(12.024,9.697) 12.695,9.697 12.894,9.499 14.674,9.499 CN2.2@14.675,9.5
  Bottom Layer w0.2: v1@12.15,9.7 X1.3@13.253,9.7
CSI_CLK_N: CN1.8 CN2.13 | length 14.5
  Top Layer w0.11: CN1.8@7.098,16.75 7.193,16.655 7.654,16.655 7.689,16.62 9.443,16.62 9.648,16.415 9.648,13.194 9.713,13.13 10.839,13.13 10.903,13.194 10.903,15.544 11.174,15.815 11.809,15.815 12.014,15.61 12.014,14.934 12.078,14.87 14.295,14.87 14.425,15 CN2.13@14.848,15
CSI_CLK_P: CN1.9 CN2.12 | length 14.5
  Top Layer w0.11: CN1.9@7.098,16.25 7.193,16.345 7.654,16.345 7.689,16.38 9.344,16.38 9.408,16.315 9.408,13.095 9.613,12.89 10.938,12.89 11.143,13.095 11.143,15.445 11.273,15.575 11.709,15.575 11.774,15.51 11.774,14.835 11.979,14.63 14.295,14.63 14.425,14.5 CN2.12@14.848,14.5
CSI_D0_N: CN1.2 CN2.16 | length 11.3
  Top Layer w0.11: CN1.2@7.098,19.75 7.448,19.75 7.578,19.62 9.043,19.62 9.718,20.295 9.922,20.295 10.177,20.55 v1(10.198,20.55) ; v1(12.797,16.872) 12.797,16.851 12.542,16.596 12.542,16.505 12.678,16.37 14.295,16.37 14.422,16.497 CN2.16@14.722,16.497
  Bottom Layer w0.11: v1(10.198,20.55) 10.219,20.55 10.474,20.295 10.843,20.295 12.668,18.469 12.668,17.151 12.923,16.896 v1@12.923,16.875
CSI_D0_P: CN1.3 CN2.15 | length 11.3
  Top Layer w0.11: CN1.3@7.098,19.25 7.193,19.345 7.654,19.345 7.689,19.38 9.142,19.38 9.817,20.055 9.922,20.055 10.177,19.8 v1(10.198,19.8) ; v1(12.047,16.872) 12.047,16.851 12.302,16.596 12.302,16.406 12.578,16.13 14.295,16.13 14.428,15.997 CN2.15@14.722,15.997
  Bottom Layer w0.11: v1(10.198,19.8) 10.219,19.8 10.474,20.055 10.743,20.055 12.428,18.37 12.428,17.151 12.173,16.896 v1@12.173,16.875
CSI_D1_N: CN1.5 CN2.19 | length 14.4
  Top Layer w0.11: CN1.5@7.098,18.25 7.193,18.155 7.654,18.155 7.689,18.12 10.593,18.12 11.708,19.236 11.708,21.802 11.913,22.007 12.993,22.007 13.198,21.802 13.198,18.598 13.926,17.87 14.295,17.87 14.425,18 CN2.19@14.675,18
CSI_D1_P: CN1.6 CN2.18 | length 14.4
  Top Layer w0.11: CN1.6@7.098,17.75 7.193,17.845 7.654,17.845 7.689,17.88 10.692,17.88 11.948,19.136 11.948,21.703 12.013,21.767 12.894,21.767 12.958,21.703 12.958,18.499 13.827,17.63 14.266,17.63 14.295,17.63 14.425,17.5 CN2.18@14.675,17.5
EN_MODULE: CN1.18 U5.5 | length 52.8
  Top Layer w0.2: CN1.18@7.053,11.75 6.1,11.75 5.525,11.175 5.525,9.025 6.375,8.175 6.375,2.675 6.775,2.275 31.925,2.275 32.5,2.85 33.8,2.85 34.375,2.275 40.025,2.275 40.6,1.7 42.9,1.7 43.425,2.225 43.425,5.575 43.603,5.753 U5.5@43.603,6.15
